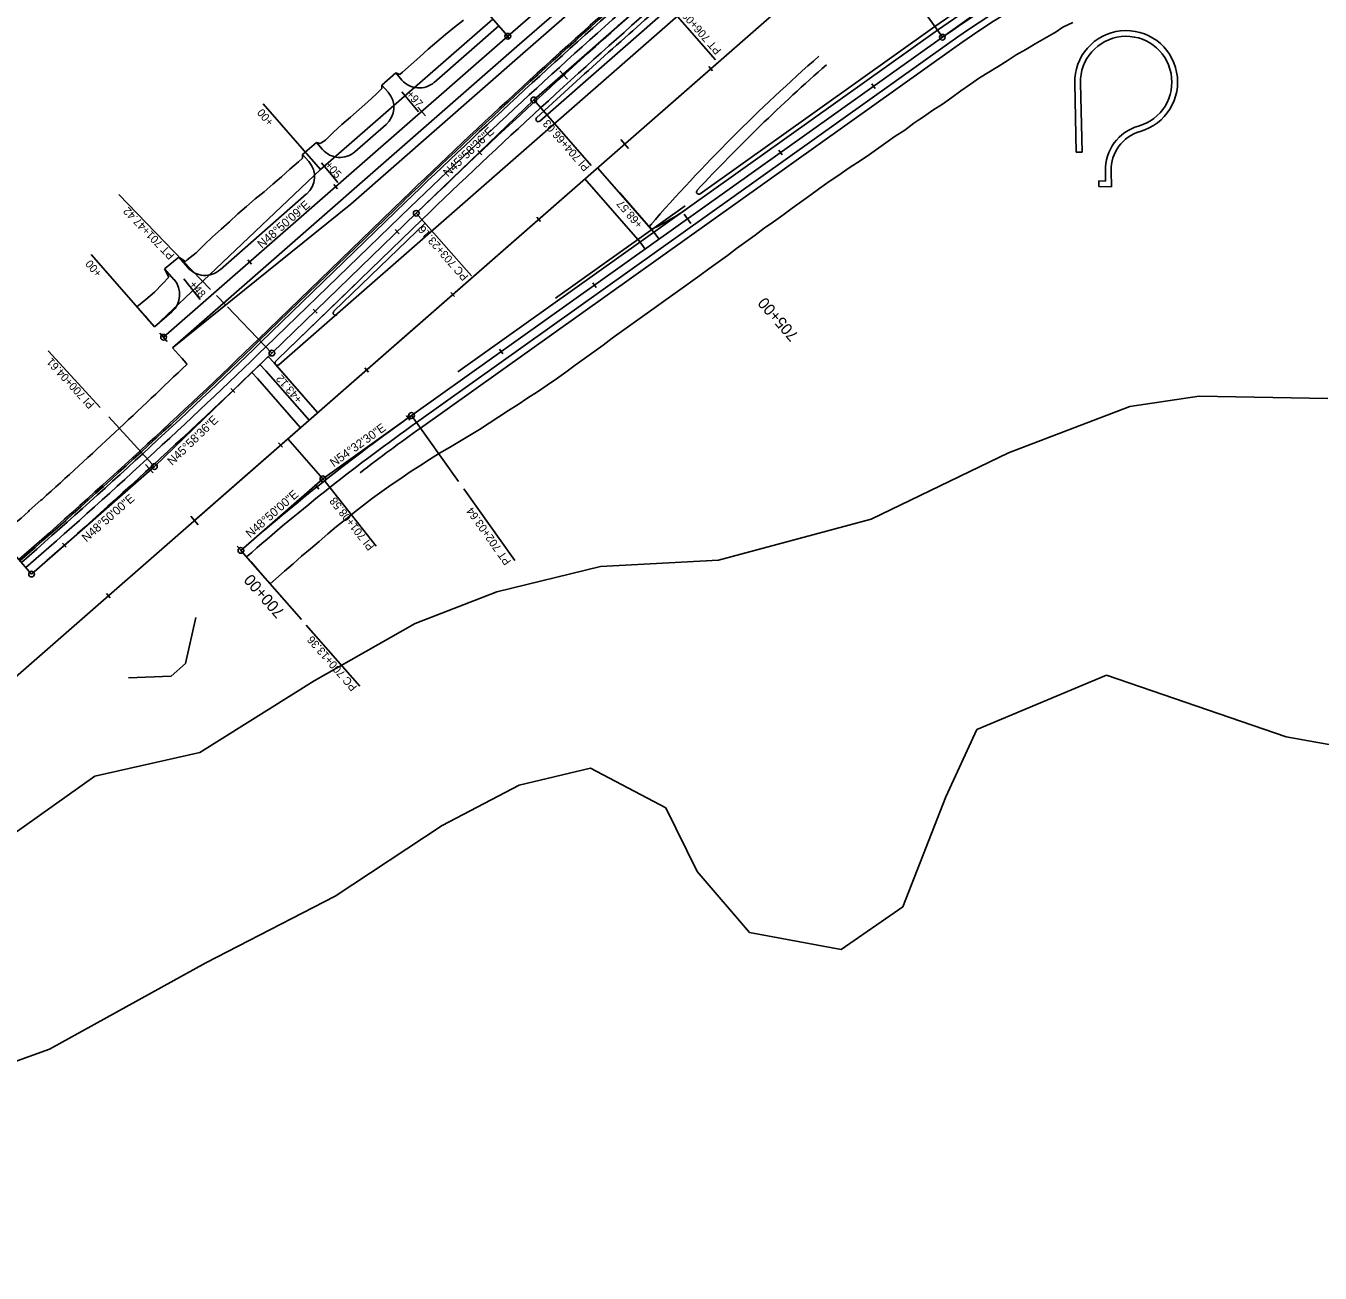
# Model space of a CAD drawing. Extents: x 1300404 to 1323571, y 237813 to 252077.
# Drawn here: x 1309033 to 1310165, y 238937 to 240028 of the extents above; entities that cross this region are included whole.
import ezdxf

# ---------------------------------------------------------------- set-up
doc = ezdxf.new("R2010")
doc.units = 0
for name, color, linetype in [('R_Barrier Wall', 7, 'Continuous'), ('R_BRIDGE OLD', 7, 'Continuous'), ('R_Const Limits', 7, 'Continuous'), ('R_Draft', 7, 'Continuous'), ('R_Flooplain', 7, 'Continuous'), ('R_Horz Alg Annot', 7, 'Continuous'), ('R_Horz Alg Annot Leader', 7, 'Continuous'), ('R_Horz Alg Major Ticks', 7, 'Continuous'), ('R_Horz Alg Minor Ticks', 7, 'Continuous'), ('R_Horz Alg Station Annot', 7, 'Continuous'), ('R_Horz Alg Tangents', 7, 'Continuous'), ('R_Horz Alg Tangents Text', 7, 'Continuous'), ('R_Lane Edge', 7, 'Continuous'), ('R_Proposed', 7, 'Continuous'), ('R_Shoulder', 7, 'Continuous')]:
    doc.layers.add(name, color=color, linetype=linetype)

msp = doc.modelspace()

# ---------------------------------------------------------------- linework, layer by layer
at = {"layer": 'R_Barrier Wall'}
for p, q in [((1309236.4, 239753.6), (1309362.7, 239875.8)), ((1309237.3, 239752.7), (1309363.7, 239874.8))]:
    msp.add_line(p, q, dxfattribs=at)
for centre, radius, start, end in [((1313356.2, 235743.8), 5746.4, 131.16667, 134.02346), ((1313356.2, 235743.8), 5745.1, 131.16667, 134.02346), ((1305266.3, 243861.4), 5712.7, 311.1667, 314.0235), ((1305266.3, 243861.4), 5714.1, 311.1667, 314.0235)]:
    msp.add_arc(centre, radius, start, end, dxfattribs=at)
at = {"layer": 'R_BRIDGE OLD'}
msp.add_line((1309302.3, 239778), (1309382.4, 239855.4), dxfattribs=at)
msp.add_arc((1309303.7, 239776.5), 2, 134.0234, 312.132, dxfattribs=at)
at = {"layer": 'R_Const Limits'}
for p, q in [((1309344.4, 239975.8), (1309356.4, 239986.4)), ((1309356.4, 239986.4), (1309360.1, 239985.2)), ((1309344.4, 239975.8), (1309344.4, 239972.7)), ((1309951.9, 239917.1), (1309950.5, 239977.5)), ((1309274.9, 239915.1), (1309287, 239925.7)), ((1309287, 239925.7), (1309290.3, 239924.6)), ((1309951.9, 239917.1), (1309956.9, 239917.2)), ((1309274.9, 239915.1), (1309275, 239911.9)), ((1309982.6, 239886.8), (1309982.3, 239900.7)), ((1309971.5, 239887), (1309971.5, 239892)), ((1309982.6, 239886.8), (1309971.5, 239887)), ((1309154.2, 239815.2), (1309166.6, 239825.3)), ((1309154.2, 239815.2), (1309157.9, 239807.8)), ((1309166.6, 239825.3), (1309172.5, 239821.5)), ((1309035.8, 239603.8), (1309046, 239612.7)), ((1309046, 239612.7), (1309047, 239613.5)), ((1309035.1, 239602.8), (1309035.8, 239603.8)), ((1309172.6, 239469.9), (1309181.6, 239510.3)), ((1309160, 239458.9), (1309172.6, 239469.9)), ((1309160, 239458.9), (1309122.5, 239457.6))]:
    msp.add_line(p, q, dxfattribs=at)
for points in [[(1309360.1, 239985.2), (1309362.5, 239987), (1309369.9, 239993.7), (1309377.4, 240000.4), (1309384.8, 240007.1), (1309392.3, 240013.7), (1309400, 240020.1), (1309407.8, 240026.4), (1309415.6, 240032.7)], [(1309948.8, 240030.5), (1309940.1, 240026.5), (1309933.4, 240021.9), (1309932.2, 240021.3), (1309924, 240016.6), (1309915.8, 240011.9), (1309907.7, 240007), (1309899.4, 240002.3), (1309891.4, 239997.1), (1309883.4, 239992.1), (1309875.3, 239987.1), (1309867.3, 239982.1), (1309859.2, 239976.6), (1309851, 239970.9), (1309843, 239964.9), (1309834.9, 239959.1), (1309826.3, 239953.8), (1309818.1, 239948.1), (1309814, 239945.3), (1309809.8, 239942.6), (1309802, 239936.3), (1309793.4, 239931.1), (1309785.2, 239925.4), (1309777.1, 239919.5), (1309768.9, 239913.8), (1309760.6, 239908.2), (1309752.2, 239902.8), (1309744, 239897), (1309735.8, 239891.4), (1309727.6, 239885.6), (1309726.4, 239884.8), (1309719.5, 239879.8), (1309711.4, 239873.9), (1309703.3, 239868.1), (1309695.2, 239862.2), (1309687.1, 239856.3), (1309678.9, 239850.6), (1309670.8, 239844.7), (1309662.7, 239838.8), (1309654.6, 239832.9), (1309647.8, 239827.7), (1309646.7, 239826.9), (1309638.6, 239821), (1309630.5, 239815.1), (1309622.4, 239809.3), (1309614.3, 239803.4), (1309611.2, 239801.2)], [(1309290.3, 239924.6), (1309294.9, 239927.6), (1309302, 239934.7), (1309309.3, 239941.5), (1309317, 239947.9), (1309324.5, 239954.6), (1309332, 239961.2), (1309339.3, 239968), (1309344.4, 239972.7)], [(1309172.5, 239821.5), (1309173.9, 239822.9), (1309181.7, 239829.2), (1309188.8, 239836.2), (1309196.2, 239843), (1309203.6, 239849.7), (1309211.1, 239856.3), (1309218.4, 239863.1), (1309226, 239869.7), (1309233.5, 239876.3), (1309241.2, 239882.6), (1309248.8, 239889.1), (1309256.5, 239895.5), (1309263.9, 239902.2), (1309271.5, 239908.8), (1309275, 239911.9)], [(1309145.4, 239764.3), (1309140.2, 239770.3), (1309137.1, 239773.9), (1309133.6, 239777.8), (1309133.2, 239778.3), (1309130, 239781.9), (1309137.7, 239788.4), (1309145.3, 239794.8), (1309152.4, 239802), (1309157.9, 239807.8)], [(1309611.2, 239801.2), (1309611.2, 239801.2), (1309603.1, 239795.4), (1309594.9, 239789.5), (1309586.7, 239783.7), (1309578.6, 239777.8), (1309570.4, 239772), (1309562.2, 239766.1), (1309554.1, 239760.2), (1309545.9, 239754.4), (1309537.8, 239748.5), (1309529.7, 239742.6), (1309521.5, 239736.7), (1309513.4, 239730.8), (1309505.3, 239724.9), (1309497.2, 239719), (1309488.9, 239713.3), (1309480.5, 239707.7), (1309472, 239702.2), (1309463.7, 239696.5), (1309455, 239691.3), (1309446.6, 239685.7), (1309438.1, 239680.2), (1309429.6, 239674.7), (1309421.1, 239669.3), (1309412.3, 239664.2), (1309403.6, 239658.9), (1309394.7, 239653.9), (1309386.1, 239648.5), (1309377.6, 239643), (1309369.2, 239637.5), (1309360.9, 239631.8), (1309352.5, 239626.2), (1309344.3, 239620.4), (1309336.2, 239614.5), (1309328.1, 239608.5), (1309320.3, 239602.3), (1309312.5, 239596), (1309304.7, 239589.7), (1309297, 239583.3), (1309289.4, 239576.8), (1309281.8, 239570.3), (1309274.1, 239563.9), (1309266.6, 239557.3), (1309259.1, 239550.7), (1309251.6, 239544.1), (1309246.5, 239539.8), (1309245.7, 239540.7), (1309236.5, 239551.3), (1309229.9, 239558.8), (1309226.3, 239563), (1309226, 239563.3), (1309226, 239563.3), (1309226, 239563.3), (1309226, 239563.3), (1309226, 239563.3)], [(1309173.8, 239731.8), (1309173.8, 239731.8), (1309173.1, 239732.7), (1309169.6, 239736.6), (1309166.5, 239740.2), (1309161.2, 239746.2)]]:
    msp.add_lwpolyline(points, dxfattribs=at)
for centre, radius, start, end in [((1309995.5, 239978.5), 45, 285.7708, 181.2933), ((1310017.3, 239901.5), 35, 105.7708, 181.2933), ((1305232.5, 243831.7), 5687.1, 312.123, 313.8707), ((1305232.5, 243831.7), 5687.1, 311.62, 311.9623)]:
    msp.add_arc(centre, radius, start, end, dxfattribs=at)
at = {"layer": 'R_Draft'}
for p, q in [((1309533.1, 239903.6), (1309582.4, 239847.2)), ((1309570.2, 239838.5), (1309521.9, 239893.8)), ((1309410.9, 239725), (1309611.4, 239867.8)), ((1309496.1, 239789.4), (1309609.6, 239870.2)), ((1309570.2, 239838.5), (1309574.6, 239832.4)), ((1309582.4, 239847.2), (1309586.8, 239841.1)), ((1309250, 239733), (1309244.8, 239738.4)), ((1309235.6, 239719.1), (1309230.4, 239724.5)), ((1309242.8, 239726), (1309237.6, 239731.4)), ((1309242.8, 239726), (1309280.6, 239682.8)), ((1309250, 239733), (1309288.1, 239689.4)), ((1309235.6, 239719.1), (1309273.1, 239676.2)), ((1309292.7, 239631.6), (1309262.1, 239666.6)), ((1309292.7, 239631.6), (1309262.1, 239666.6))]:
    msp.add_line(p, q, dxfattribs=at)
msp.add_arc((1309580.8, 239852.1), 2, 98.9101, 305.4583, dxfattribs=at)
at = {"layer": 'R_Flooplain'}
for p, q in [((1310059.5, 239703.8), (1309998.6, 239694.8)), ((1310171.9, 239701.8), (1310059.5, 239703.8)), ((1309998.6, 239694.8), (1309892.5, 239654.2)), ((1309892.5, 239654.2), (1309772.3, 239596.1)), ((1309772.3, 239596.1), (1309638.7, 239560.5)), ((1309535.5, 239554.8), (1309444.9, 239532.8)), ((1309638.7, 239560.5), (1309535.5, 239554.8)), ((1309444.9, 239532.8), (1309373.4, 239504.9)), ((1309373.4, 239504.9), (1309285, 239454.9)), ((1309285, 239454.9), (1309185.1, 239392.2)), ((1309864.8, 239412.4), (1309978.4, 239459.9)), ((1309978.4, 239459.9), (1310135.4, 239406)), ((1309837.6, 239353.3), (1309864.8, 239412.4)), ((1310135.4, 239406), (1310345.2, 239367.6)), ((1309185.1, 239392.2), (1309093.3, 239371.4)), ((1309464.3, 239363.6), (1309526.8, 239378.6)), ((1309526.8, 239378.6), (1309592.8, 239343.8)), ((1308757.3, 239134.3), (1309093.3, 239371.4)), ((1309397.2, 239328.3), (1309464.3, 239363.6)), ((1309800.2, 239257.2), (1309837.6, 239353.3)), ((1309592.8, 239343.8), (1309620.3, 239288)), ((1309303.4, 239266.5), (1309397.2, 239328.3)), ((1309620.3, 239288), (1309666, 239234.9)), ((1309190.4, 239208.1), (1309303.4, 239266.5)), ((1309746.3, 239220), (1309800.2, 239257.2)), ((1309666, 239234.9), (1309746.3, 239220)), ((1309053.6, 239132.7), (1309190.4, 239208.1)), ((1308935.3, 239090.2), (1309053.6, 239132.7))]:
    msp.add_line(p, q, dxfattribs=at)
at = {"layer": 'R_Horz Alg Annot Leader'}
for p, q in [((1309290.7, 239902), (1309240.4, 239959.5)), ((1309579.3, 239850.8), (1309552.4, 239881.5)), ((1309145.4, 239764.3), (1309090.1, 239827.6)), ((1309280.1, 239698.5), (1309251.3, 239731.5))]:
    msp.add_line(p, q, dxfattribs=at)
for points in [[(1309345.2, 240143.6), (1309454.5, 240018.5)], [(1309834.7, 240017.7), (1309772.4, 240105.2)], [(1309584.7, 240057), (1309636.3, 239998)], [(1309376.5, 239952.4), (1309361.8, 239969.9)], [(1309527.3, 239905.6), (1309477.2, 239962.9)], [(1309305.9, 239890.7), (1309291.5, 239907.8)], [(1309194.3, 239797.2), (1309114.2, 239880.1)], [(1309374.4, 239863.7), (1309422.6, 239809.1)], [(1309171.1, 239806.4), (1309185.3, 239788.2)], [(1309207.7, 239783.3), (1309199.5, 239791.8)], [(1309248.1, 239741.5), (1309209.1, 239781.8)], [(1309052.2, 239743.5), (1309097.9, 239693.8)], [(1309105.3, 239685.8), (1309143.4, 239644.3)], [(1309370.3, 239686.9), (1309411.3, 239629.2)], [(1309144.7, 239643), (1309145.3, 239642.2)], [(1309292.7, 239631.6), (1309293.6, 239630.5)], [(1309294.7, 239629.1), (1309339.2, 239572.7)], [(1309416, 239622.7), (1309460.5, 239560.2)], [(1309037.8, 239548.2), (1308998, 239593.6)], [(1309221, 239568.9), (1309274, 239508.4)], [(1309278.2, 239503.6), (1309325, 239450.1)]]:
    msp.add_lwpolyline(points, dxfattribs=at)
at = {"layer": 'R_Horz Alg Major Ticks'}
for points in [[(1309500.1, 239988.3), (1309506.8, 239980.9)], [(1309375.9, 239956.5), (1309382.5, 239949)], [(1309553.5, 239928.1), (1309560.1, 239920.5)], [(1309608.8, 239862.9), (1309614.6, 239854.7)], [(1309150, 239759), (1309156.6, 239751.5)], [(1309150, 239759), (1309156.6, 239751.5)], [(1309137.4, 239644.1), (1309144.1, 239636.8)], [(1309177.1, 239598.9), (1309183.7, 239591.4)], [(1309217.7, 239572.7), (1309224.3, 239565.2)], [(1309217.7, 239572.7), (1309224.3, 239565.2)]]:
    msp.add_lwpolyline(points, dxfattribs=at)
at = {"layer": 'R_Horz Alg Minor Ticks'}
for points in [[(1309452.8, 240020.4), (1309456.1, 240016.7)], [(1309630.4, 239992), (1309633.7, 239988.2)], [(1309773.1, 239976.8), (1309776, 239972.8)], [(1309428.3, 239918.5), (1309431.8, 239914.9)], [(1309691.7, 239918.8), (1309694.6, 239914.8)], [(1309302.3, 239888.8), (1309305.6, 239885)], [(1309479.8, 239860.3), (1309483.1, 239856.6)], [(1309356, 239849.4), (1309359.5, 239845.8)], [(1309227, 239823), (1309230.3, 239819.2)], [(1309404.6, 239794.5), (1309407.9, 239790.8)], [(1309528.8, 239802.8), (1309531.7, 239798.7)], [(1309284.1, 239779.9), (1309287.6, 239776.3)], [(1309151.7, 239757.1), (1309155, 239753.4)], [(1309447.3, 239744.8), (1309450.2, 239740.7)], [(1309329.3, 239728.7), (1309332.6, 239724.9)], [(1309212.1, 239710.5), (1309215.6, 239706.9)], [(1309365.9, 239686.8), (1309368.8, 239682.7)], [(1309254, 239662.9), (1309257.3, 239659.1)], [(1309286, 239626.4), (1309289.1, 239622.5)], [(1309064.8, 239575.3), (1309068.2, 239571.6)], [(1309103.4, 239531.2), (1309106.7, 239527.5)]]:
    msp.add_lwpolyline(points, dxfattribs=at)
at = {"layer": 'R_Horz Alg Tangents'}
for p, q in [((1309834.7, 240017.7), (1309983.8, 240123.8)), ((1309477.2, 239962.9), (1309584.7, 240057)), ((1309374.4, 239863.7), (1309477.2, 239962.9)), ((1309145.3, 239642.2), (1309248.1, 239741.5)), ((1309292.7, 239631.6), (1309370.3, 239686.9)), ((1309037.8, 239548.2), (1309145.3, 239642.2)), ((1309221, 239568.9), (1309292.7, 239631.6))]:
    msp.add_line(p, q, dxfattribs=at)
at = {"layer": 'R_Lane Edge'}
for p, q in [((1309254.1, 239731.3), (1311026.8, 241281.4)), ((1309462.4, 240009.5), (1309652.9, 240175.6)), ((1309390.1, 239978.2), (1309446.6, 240027.6)), ((1309611.4, 239867.8), (1309830.4, 240023.8)), ((1309161.2, 239746.2), (1309462.4, 240009.5)), ((1309374.6, 239680.8), (1309839.1, 240011.5)), ((1309344.4, 239975.8), (1309356.4, 239986.4)), ((1309356.4, 239986.4), (1309361.9, 239980.1)), ((1309344.4, 239975.8), (1309349.8, 239969.6)), ((1309956.9, 239917.2), (1309955.5, 239977.6)), ((1309320.7, 239917.5), (1309348, 239941.4)), ((1309274.9, 239915.1), (1309287, 239925.7)), ((1309287, 239925.7), (1309292.5, 239919.4)), ((1309274.9, 239915.1), (1309280.4, 239908.9)), ((1309977.5, 239891.9), (1309977.3, 239900.6)), ((1309977.5, 239891.9), (1309971.5, 239892)), ((1309202.7, 239814.4), (1309278.5, 239880.6)), ((1309242.8, 239746.9), (1309369.2, 239869)), ((1309253.3, 239736.1), (1309379.6, 239858.3)), ((1309154.2, 239815.2), (1309166.6, 239825.3)), ((1309154.2, 239815.2), (1309162.4, 239805.7)), ((1309166.6, 239825.3), (1309174.5, 239816.3)), ((1309253.3, 239736.1), (1309322, 239802.5)), ((1309145.4, 239764.3), (1309160.5, 239777.5))]:
    msp.add_line(p, q, dxfattribs=at)
for centre, radius, start, end in [((1310388.7, 239239.8), 962.4, 103.7556, 125.4583), ((1310388.7, 239239.8), 947.4, 103.7556, 125.4583), ((1313356.2, 235743.8), 5737.1, 131.16667, 134.02346), ((1313356.2, 235743.8), 5722.1, 131.1667, 134.0235), ((1309995.5, 239978.5), 40, 285.7708, 181.2933), ((1310770.2, 238812.1), 1582, 131.2681, 138.8338), ((1309376.9, 239993.3), 20, 221.1641, 311.1641), ((1309334.8, 239956.4), 20, 311.1641, 41.1641), ((1310017.3, 239901.5), 40, 105.7708, 181.2933), ((1309307.5, 239932.6), 20, 221.1641, 311.1641), ((1309265.4, 239895.7), 20, 311.1641, 41.1641), ((1309486.7, 240046), 217.5, 295.8741, 304.9655), ((1309580.8, 239852.1), 2, 138.8331, 295.8874), ((1309189.5, 239829.4), 20, 221.1641, 311.1641), ((1309147.4, 239792.6), 20, 311.1641, 41.1641), ((1305266.3, 243861.4), 5722.1, 311.1667, 314.0235), ((1305266.3, 243861.4), 5737.1, 313.99693, 314.02346), ((1309252.8, 239732.8), 2, 134.0235, 311.1667), ((1310478.2, 238131.2), 1902.4, 125.4583, 131.1667)]:
    msp.add_arc(centre, radius, start, end, dxfattribs=at)
at = {"layer": 'R_Proposed'}
for p, q in [((1308427.6, 238936.9), (1312793.8, 242754.8)), ((1309180.4, 239595.2), (1312399, 242409.5)), ((1309454.5, 240018.5), (1309645, 240184.6)), ((1309153.3, 239755.3), (1309454.5, 240018.5)), ((1309370.3, 239686.9), (1309834.7, 240017.7)), ((1309370.3, 239686.9), (1309834.7, 240017.7)), ((1309370.3, 239686.9), (1309834.7, 240017.7)), ((1309248.1, 239741.5), (1309374.4, 239863.7))]:
    msp.add_line(p, q, dxfattribs=at)
for centre in [(1309454.5, 240018.5), (1309834.7, 240017.7), (1309477.2, 239962.9), (1309374.4, 239863.7), (1309153.3, 239755.3), (1309248.1, 239741.5), (1309370.3, 239686.9), (1309145.3, 239642.2), (1309292.7, 239631.6), (1309221, 239568.9), (1309037.8, 239548.2)]:
    msp.add_circle(centre, 2.5, dxfattribs=at)
for centre, radius, start, end in [((1310388.7, 239239.8), 954.9, 103.7556, 125.4583), ((1310388.7, 239239.8), 954.9, 104.2118, 125.4583), ((1310388.7, 239239.8), 954.9, 104.2118, 125.4583), ((1313356.2, 235743.8), 5729.6, 131.16667, 134.02346), ((1305266.3, 243861.4), 5729.6, 311.16667, 314.02346), ((1310478.2, 238131.2), 1909.9, 125.4583, 131.1667), ((1310478.2, 238131.2), 1909.9, 125.4583, 131.1667), ((1310478.2, 238131.2), 1909.9, 125.4583, 131.1667)]:
    msp.add_arc(centre, radius, start, end, dxfattribs=at)
at = {"layer": 'R_Shoulder'}
for p, q in [((1309482.4, 239944.3), (1311020.2, 241289)), ((1309467.6, 240003.5), (1309658.1, 240169.6)), ((1309363.7, 239965.7), (1309441.3, 240033.6)), ((1309622.8, 239880.8), (1309828.1, 240027)), ((1309317.1, 239871.8), (1309467.6, 240003.5)), ((1309378.1, 239675.9), (1309842.6, 240006.7)), ((1309290.7, 239902), (1309363.7, 239965.7)), ((1309290.7, 239902), (1309193.5, 239809.8)), ((1309317.1, 239871.8), (1309161.2, 239746.2)), ((1309238.7, 239751.2), (1309365, 239873.4)), ((1309193.5, 239809.8), (1309145.4, 239764.3))]:
    msp.add_line(p, q, dxfattribs=at)
for centre, radius, start, end in [((1310388.7, 239239.8), 966.4, 103.7556, 125.4583), ((1310388.7, 239239.8), 941.4, 103.7556, 125.4583), ((1313356.2, 235743.8), 5743.1, 131.16667, 134.02346), ((1313356.2, 235743.8), 5718.1, 131.1667, 132.683), ((1310770.2, 238812.1), 1572, 131.2681, 137.0202), ((1309481.1, 239945.8), 2, 132.683, 311.1667), ((1309621.6, 239882.4), 2, 137.0202, 305.4583), ((1305266.3, 243861.4), 5716.1, 311.1667, 314.0235), ((1310478.2, 238131.2), 1896.4, 125.4583, 127.4446)]:
    msp.add_arc(centre, radius, start, end, dxfattribs=at)

# ---------------------------------------------------------------- texts
at = {"layer": 'R_Horz Alg Annot'}
for s, rotation, p in [('PT 706+08.84', 131.1667, (1309641.8, 240006.3)), ('+97', 311.3153, (1309365.2, 239967.5)), ('+00', 130.5769, (1309250.2, 239943.8)), ('PI 704+66.03', 131.1667, (1309526.6, 239904.2)), ('+05', 311.3153, (1309294, 239905.5)), ('+68.57', 130.5769, (1309573.2, 239854.2)), ('PT 701+47.42', 134.0235, (1309163.4, 239827.3)), ('PC 703+23.16', 131.4363, (1309420.5, 239808.5)), ('+00', 130.5769, (1309099.9, 239811.6)), ('+48', 309.871, (1309175.3, 239801.2)), ('PI 700+04.61', 132.5951, (1309093.3, 239696.7)), ('+43.12', 130.5769, (1309275.2, 239701.3)), ('PI 701+08.58', 128.3125, (1309338.1, 239572.3)), ('PT 702+03.64', 125.4583, (1309457.7, 239559.2)), ('PC 700+13.36', 131.1667, (1309323.1, 239449.6))]:
    msp.add_text(s, height=7, rotation=rotation, dxfattribs=at).set_placement(p)
at = {"layer": 'R_Horz Alg Station Annot'}
for s, p in [('705+00', (1309709.5, 239757.3)), ('700+00', (1309259.9, 239515.2))]:
    msp.add_text(s, height=10, rotation=131.1667, dxfattribs=at).set_placement(p)
at = {"layer": 'R_Horz Alg Tangents Text'}
for s, rotation, p in [('N45%%d58\'36"E', 44.0235, (1309402.2, 239895)), ('N48%%d50\'09"E', 41.0808, (1309239.3, 239832.6)), ('N45%%d58\'36"E', 44.0235, (1309160.9, 239642.7)), ('N54%%d32\'30"E', 35.4583, (1309302.2, 239641.5)), ('N48%%d50\'00"E', 41.1667, (1309085.8, 239575.8)), ('N48%%d50\'00"E', 41.1667, (1309229.2, 239579.4))]:
    msp.add_text(s, height=7.5, rotation=rotation, dxfattribs=at).set_placement(p)

doc.saveas('drawing.dxf')
